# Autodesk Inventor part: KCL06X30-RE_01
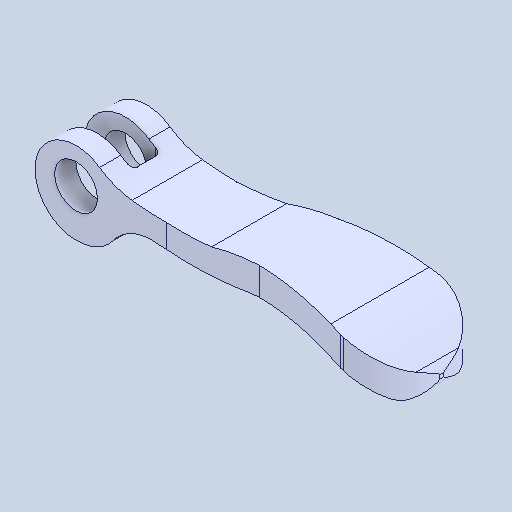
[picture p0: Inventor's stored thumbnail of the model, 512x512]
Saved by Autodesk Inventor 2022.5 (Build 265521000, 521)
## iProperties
Created: 2024-08
Part Number: KCL06X30-RE_01
Material: 一般
Document SubType Name: Modeling
Designer: ImaoCorp
Density: 1 g/cm^3
Appearance: 既定
Author: ImaoCorp
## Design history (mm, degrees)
feature "KCL06X30-RE_01"
node "ソリッド1"
